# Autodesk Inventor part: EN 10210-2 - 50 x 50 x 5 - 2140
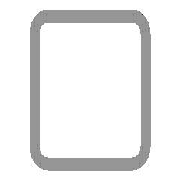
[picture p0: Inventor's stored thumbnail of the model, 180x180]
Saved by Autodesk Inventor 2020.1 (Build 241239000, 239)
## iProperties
Created: 2019-01
Part Number: EN 10210-2 - 50 x 50 x 5 - 2140
Material: Stahl, weich
Description: Rohrleitung
Document SubType Name: Modeling
Standard: DIN
Designer: lutzd
Standard Revision: 2006-07
Standards Organization: DIN
Language: de-DE
Size Designation: 50 x 50 x 5
Categories: <MemberInstance><Categories><Category DisplayName="Profile" InternalName="089c4875-fa83-4c05-b084-43b9cc11f5ed" Mnemonic="GRDR"><CategoryParameter DisplayName="
Stock Number: 50 x 50 x 5
Mass: 14665.7 g
Surface Area: 7262.92 cm^2
Volume: 1868.25 cm^3
Density: 7.85 g/cm^3
Appearance: Halbpoliert
IsCustomPart: 1
G_L: 2140,000 mm
G_W: 50,000 mm
G_H: 50,000 mm
DocNumber: ADSK-014212
Folder: .
Dimensions: 50x50x2140 mm
Mass: 14,666 kg
+65A53621-0317-4F01-B8AC-9A0CFF2618E3+SCHNITTDETAIL1: Schnittwinkel 90,00 grd
+93927B57-8D45-4040-A888-B30C7E95A323+SCHNITTDETAIL2: Schnittwinkel 90,00 grd
_CCFamilyMember: 16
_CCFamilyDisplayName: DIN EN 10210-2 (USAS B17.1 quadratisch) - Rohrleitung — In Klammern angegebene Größen wurden aufgehoben
_FrameMemberDoc: Frame Member File
_Version: 15.0.0
_GetPNFromCC: 1
Title: Profil-Bauteil
Author: lutzd
Revision Number: -
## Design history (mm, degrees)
node "Startebene"
node "Endebene"
sketch "Skizze"
  geometry: L1 (-25, -17.5)-(-25, 17.5); L2 (-17.5, 25)-(17.5, 25); L3 (25, 17.5)-(25, -17.5); L4 (17.5, -25)-(-17.5, -25); L5 (-15, 20)-(15, 20); L6 (20, 15)-(20, -15); L7 (15, -20)-(-15, -20); L8 (-20, -15)-(-20, 15); L9 (0, 37.175)-(0, -37.175) reference; L10 (-37.175, 0)-(37.175, 0) reference; A1 r 7.5 centre (-17.5, -17.5) between (-25, -17.5) and (-17.5, -25); A2 r 7.5 centre (-17.5, 17.5) between (-17.5, 25) and (-25, 17.5); A3 r 7.5 centre (17.5, 17.5) between (25, 17.5) and (17.5, 25); A4 r 7.5 centre (17.5, -17.5) between (17.5, -25) and (25, -17.5); A5 r 5 centre (-15, -15) between (-20, -15) and (-15, -20); A6 r 5 centre (-15, 15) between (-15, 20) and (-20, 15); A7 r 5 centre (15, 15) between (20, 15) and (15, 20); A8 r 5 centre (15, -15) between (15, -20) and (20, -15)
  constraints: 16 end point, 16 point on circle, 16 tangent, 8 centre point, 6 equal radius, 4 parallel, 2 perpendicular, 2 other
  dimensions: "d7" = 7.5 radius of A1 (= G_IR); "d10" = 50 distance between parallel lines of L2 L4 (= G_H); "d11" = 50 distance between parallel lines of L1 L3 (= G_W); "d12" = 5 distance between parallel lines of L3 L6 (= G_T); "d15" = 25 distance between parallel lines of L2 L10 (= 0.5 x d10); "d16" = 25 distance between parallel lines of L9 L3 (= 0.5 x d11); "d19" = 5 radius of A5 (= G_T); "d20" = 5 distance between parallel lines of L4 L7 (= G_T)
extrude "Körper" new body sketch "Skizze" stored distance "d3" = 2140 (= G_L); taper "d4" = 0 deg
node "Driven Length"
  sketch "Sketch3"
    geometry: L1 (0, 0)-(10, 0) reference
    constraints: 2 end point, 1 horizontal
  workplane "Work Plane3"
  sketch "Sketch4"
    geometry: L1 (-2, 35)-(12, 35) reference; L2 (-2, 2175)-(12, 2175) reference
    dimensions: "d18" = 2140 distance between parallel lines of L1 L2 (derived)
workplane "Arbeitsebene4"
feature "Trennen1"
workplane "Arbeitsebene5"
feature "Trennen2"
sketch "Skizze5"
  geometry: L1 (1125, 0)-(1125, 35) reference; L2 (1125, 17.5)-(889, 17.5); 3 further points
  constraints: 4 end point, 1 coincident, 1 midpoint, 1 perpendicular, 1 point on line, 1 vertical, 2 other
  dimensions: "d21" = 64 distance of point (953, 17.5) point (889, 17.5); "d22" = 172 distance of L2.start point (953, 17.5)
hole "Bohrung1" sketch "Skizze5" at (889, 17.5), (953, 17.5) diameter "d23" = 6.647; stored, may be unused: countersink angle "d27" = 90 deg, drill point angle "d29" = 118 deg; dims "d24" = 16, "d25" = 15, "d26" = 9, "d28" = 22.2
body "Solid1"
other parameters: "G_W" = 50 [user parameter; used in 1 equation term], "G_H" = 50 [user parameter; used in 1 equation term], "G_T" = 5 [user parameter; used in 3 equation terms], "G_IR" = 7.5 [user parameter; used in 1 equation term], "G_L" = 2140 (= d18) [user parameter; used in 1 equation term], "G_OFFSET_START" = -35 [user parameter; used in 1 equation term], "d13" = 35 (= -G_OFFSET_START), "d14" = 2175 (= G_OFFSET_END + B_L), "B_L" = 2225 [user parameter; used in 1 equation term], "d17" = 90 deg
